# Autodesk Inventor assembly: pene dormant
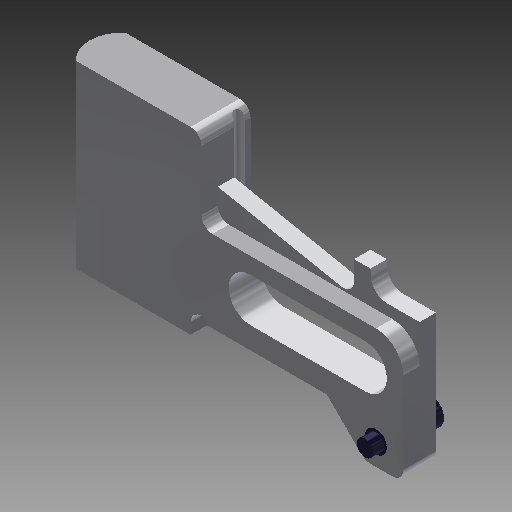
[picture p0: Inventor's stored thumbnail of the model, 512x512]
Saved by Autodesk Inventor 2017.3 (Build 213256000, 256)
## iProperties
Created: 2007-11
Part Number: pene dormant
Material: Générique
Document SubType Name: Assembly
Designer: ficho
Author: ficho
Sending System: SolidWorks 2009
Last Author: christophe
Last Saved: 2011-02-10
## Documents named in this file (3)
- G:\travail\année 2019-2020\réforme\toussaint\Serrure biométrique SET\Documentations_pedagogique\Modelisation_Solidworks\pene dormant.iam
- G:\travail\année 2019-2020\réforme\toussaint\Serrure biométrique SET\Documentations_pedagogique\Modelisation_Solidworks\Pièce11.ipt
- G:\travail\année 2019-2020\réforme\toussaint\Serrure biométrique SET\Documentations_pedagogique\Modelisation_Solidworks\Pièce12.ipt
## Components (2 placed, 2 different names)
1. Pièce11:1
2. Pièce12:1
